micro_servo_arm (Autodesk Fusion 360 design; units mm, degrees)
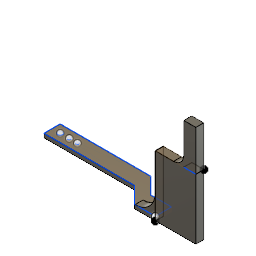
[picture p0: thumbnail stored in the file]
sketch "Sketch1" plane through (0, 0, 0) normal (0, 1, 0) x axis (1, 0, 0)
  line L1 (-20.7028, 11.983) -> (-20.7028, 19.983)
  line L2 (-83.6695, 28.0031) -> (-83.6695, 20.0031)
  line L3 (-20.7028, 19.983) -> (-30.9798, 19.983)
  line L4 (-20.7028, 11.983) -> (-30.9798, 11.983)
  line L5 (-39, 20.0031) -> (-30.9798, 11.983)
  line L6 (-39, 28.0031) -> (-30.9798, 19.983)
  line L7 (-42, 20.0031) -> (-39, 20.0031)
  line L8 (-83.6695, 20.0031) -> (-65, 20.0031)
  line L9 (-42, 28.0031) -> (-39, 28.0031)
  line L10 (-83.6695, 28.0031) -> (-65, 28.0031)
  line L11 (-42, 28.0031) -> (-65, 28.0031)
  line L12 (-42, 20.0031) -> (-65, 20.0031)
  circle C1 centre (-75.1695, 24.0034) radius 0.75
  circle C2 centre (-79.6695, 24.0334) radius 1.2
  circle C3 centre (-71.1695, 24.0036) radius 0.75
  dimension "d60" diameter C1 = 1.5
  dimension "d62" diameter C3 = 1.5
extrude "Extrude1" new body sketch "Sketch1" profile of L1 L2 C1 C2 C3 L3 L4 L10 L8 L5 L6 against normal blind 2
sketch "Sketch3" plane through (-20.7028, 0, 0) normal (1, 0, 0) x axis (0, 0, -1)
  line L1 (11.983, 0) -> (19.983, 0)
  line L2 (11.983, -2) -> (11.983, 0)
  line L3 (19.983, -2) -> (11.983, -2)
  line L4 (19.983, 0) -> (19.983, -2)
  line L5 (15.983, -2) -> (11.983, -2)
  line L6 (15.983, 28) -> (15.983, -2)
  line L7 (11.983, 28) -> (15.983, 28)
  line L8 (11.983, -2) -> (11.983, 28)
  point P6 (11.983, -2)
  point P7 (15.983, -2)
  dimension "d49" distance P6 P7 = 4
  dimension "d50" distance L5 L7 = 30
extrude "Extrude4" add sketch "Sketch3" profile of L1 L2 L3 L5 L6 L7 L8 along normal blind 20
fillet "Fillet7" radius 10
fillet "Fillet8" radius 5
sketch "Sketch4" plane through (0, 28, 0) normal (0, 1, 0) x axis (-1, 0, 0)
  line L1 (20.7028, -11.983) -> (20.7028, -15.983)
  line L2 (0.7028, -11.983) -> (20.7028, -11.983)
  line L3 (0.7028, -15.983) -> (0.7028, -11.983)
  line L4 (20.7028, -15.983) -> (0.7028, -15.983)
  line L5 (6.7028, -15.983) -> (0.7028, -15.983)
  line L6 (6.7028, -11.983) -> (6.7028, -15.983)
  line L7 (0.7028, -11.983) -> (6.7028, -11.983)
  line L8 (0.7028, -15.983) -> (0.7028, -11.983)
  point P6 (0.7028, -15.983)
  point P7 (6.7028, -15.983)
  dimension "d56" distance P6 P7 = 6
extrude "Extrude5" add sketch "Sketch4" profile of L2 L3 L4 L5 L6 L7 L8 along normal blind 20
fillet "Fillet9" radius 5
